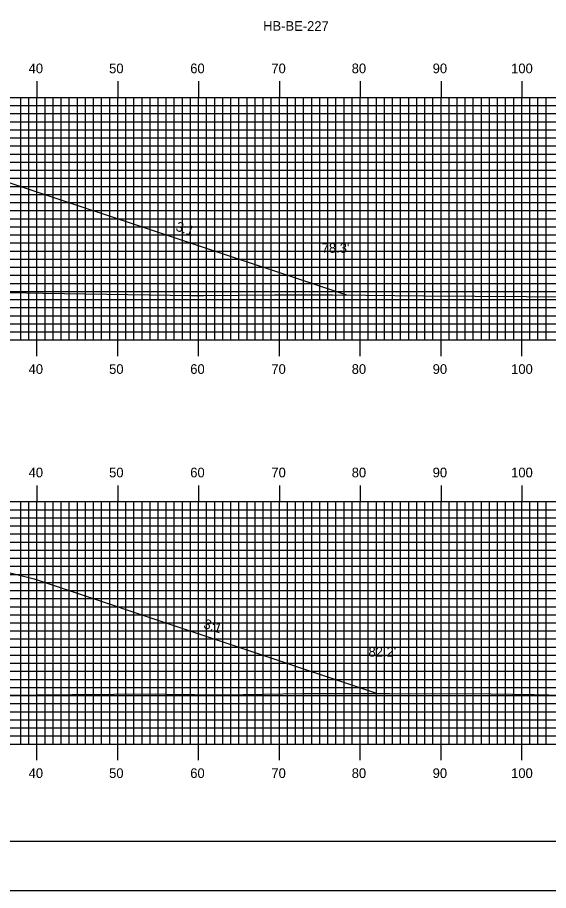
# Model space of a CAD drawing. Extents: x 1786976 to 1787319, y 442591 to 442811.
# Drawn here: x 1787179.2 to 1787244.9, y 442590.5 to 442698.6 of the extents above; entities that cross this region are included whole.
import ezdxf

# ---------------------------------------------------------------- set-up
doc = ezdxf.new("R2010")
doc.units = 0
for name, color, linetype in [('ANNOTATION', 7, 'Continuous'), ('BORDER', 7, 'Continuous'), ('BORING - NO REFUSAL', 7, 'Continuous'), ('D_Roadway_Centerline', 7, 'Continuous'), ('D_Roadway_SlopeLines', 7, 'Continuous'), ('D_Text_Standard', 7, 'Continuous'), ('H_V ANNOTATION', 7, 'Continuous'), ('MAJOR', 7, 'Continuous'), ('MINOR', 7, 'Continuous'), ('PLOT BOUNDARY', 7, 'Continuous'), ('S_Roadway_Centerline', 7, 'Continuous')]:
    doc.layers.add(name, color=color, linetype=linetype)

msp = doc.modelspace()

# ---------------------------------------------------------------- linework, layer by layer
at = {"layer": 'BORDER'}
msp.add_lwpolyline([(1786991.99, 442596.67), (1787311.99, 442596.67), (1787311.99, 442806.67), (1786991.99, 442806.67)], close=True, dxfattribs=at)
at = {"layer": 'D_Roadway_Centerline'}
for points in [[(1787075.17, 442666.66), (1787111.2, 442678.66), (1787118.59, 442681.13), (1787121.59, 442681.25), (1787129.59, 442681.57), (1787141.59, 442681.83), (1787153.59, 442682.1), (1787166.23, 442681.59), (1787174.6, 442679.18), (1787178.23, 442678.13), (1787219.9, 442664.24)], [(1787073.18, 442616.62), (1787111.2, 442629.29), (1787118.59, 442631.76), (1787121.59, 442631.88), (1787129.59, 442632.2), (1787141.59, 442632.46), (1787153.59, 442632.72), (1787169.26, 442632.1), (1787178.77, 442629.72), (1787181.26, 442629.1), (1787223.75, 442614.93)]]:
    msp.add_lwpolyline(points, dxfattribs=at)
at = {"layer": 'D_Roadway_SlopeLines'}
for points in [[(1787166.23, 442681.59), (1787178.23, 442678.13), (1787219.9, 442664.24)], [(1787169.26, 442632.1), (1787181.26, 442629.1), (1787223.75, 442614.93)]]:
    msp.add_lwpolyline(points, dxfattribs=at)
at = {"layer": 'MAJOR'}
for p, q in [((1787181.59, 442690.67), (1787181.59, 442688.67)), ((1787191.59, 442690.67), (1787191.59, 442688.67)), ((1787201.59, 442690.67), (1787201.59, 442688.67)), ((1787211.59, 442690.67), (1787211.59, 442688.67)), ((1787221.59, 442690.67), (1787221.59, 442688.67)), ((1787231.59, 442690.67), (1787231.59, 442688.67)), ((1787241.59, 442690.67), (1787241.59, 442688.67)), ((1787001.59, 442688.67), (1787281.59, 442688.67)), ((1787001.59, 442688.67), (1787281.59, 442688.67)), ((1787181.59, 442658.67), (1787181.59, 442688.67)), ((1787191.59, 442658.67), (1787191.59, 442688.67)), ((1787201.59, 442658.67), (1787201.59, 442688.67)), ((1787211.59, 442658.67), (1787211.59, 442688.67)), ((1787221.59, 442658.67), (1787221.59, 442688.67)), ((1787231.59, 442658.67), (1787231.59, 442688.67)), ((1787241.59, 442658.67), (1787241.59, 442688.67)), ((1787001.59, 442683.67), (1787281.59, 442683.67)), ((1787001.59, 442678.67), (1787281.59, 442678.67)), ((1787001.59, 442673.67), (1787281.59, 442673.67)), ((1787001.59, 442668.67), (1787281.59, 442668.67)), ((1787001.59, 442663.67), (1787281.59, 442663.67)), ((1787001.59, 442658.67), (1787281.59, 442658.67)), ((1787001.59, 442658.67), (1787281.59, 442658.67)), ((1787181.59, 442656.66), (1787181.59, 442658.67)), ((1787191.59, 442656.66), (1787191.59, 442658.67)), ((1787201.59, 442656.66), (1787201.59, 442658.67)), ((1787211.59, 442656.66), (1787211.59, 442658.67)), ((1787221.59, 442656.66), (1787221.59, 442658.67)), ((1787231.59, 442656.66), (1787231.59, 442658.67)), ((1787241.59, 442656.66), (1787241.59, 442658.67)), ((1787181.59, 442640.67), (1787181.59, 442638.67)), ((1787191.59, 442640.67), (1787191.59, 442638.67)), ((1787201.59, 442640.67), (1787201.59, 442638.67)), ((1787211.59, 442640.67), (1787211.59, 442638.67)), ((1787221.59, 442640.67), (1787221.59, 442638.67)), ((1787231.59, 442640.67), (1787231.59, 442638.67)), ((1787241.59, 442640.67), (1787241.59, 442638.67)), ((1787001.59, 442638.67), (1787281.59, 442638.67)), ((1787001.59, 442638.67), (1787281.59, 442638.67)), ((1787181.59, 442608.67), (1787181.59, 442638.67)), ((1787191.59, 442608.67), (1787191.59, 442638.67)), ((1787201.59, 442608.67), (1787201.59, 442638.67)), ((1787211.59, 442608.67), (1787211.59, 442638.67)), ((1787221.59, 442608.67), (1787221.59, 442638.67)), ((1787231.59, 442608.67), (1787231.59, 442638.67)), ((1787241.59, 442608.67), (1787241.59, 442638.67)), ((1787001.59, 442633.67), (1787281.59, 442633.67)), ((1787001.59, 442628.67), (1787281.59, 442628.67)), ((1787001.59, 442623.67), (1787281.59, 442623.67)), ((1787001.59, 442618.67), (1787281.59, 442618.67)), ((1787001.59, 442613.67), (1787281.59, 442613.67)), ((1787001.59, 442608.67), (1787281.59, 442608.67)), ((1787001.59, 442608.67), (1787281.59, 442608.67)), ((1787181.59, 442606.66), (1787181.59, 442608.67)), ((1787191.59, 442606.66), (1787191.59, 442608.67)), ((1787201.59, 442606.66), (1787201.59, 442608.67)), ((1787211.59, 442606.66), (1787211.59, 442608.67)), ((1787221.59, 442606.66), (1787221.59, 442608.67)), ((1787231.59, 442606.66), (1787231.59, 442608.67)), ((1787241.59, 442606.66), (1787241.59, 442608.67))]:
    msp.add_line(p, q, dxfattribs=at)
at = {"layer": 'MINOR'}
for p, q in [((1787179.59, 442658.67), (1787179.59, 442688.67)), ((1787180.59, 442658.67), (1787180.59, 442688.67)), ((1787182.59, 442658.67), (1787182.59, 442688.67)), ((1787183.59, 442658.67), (1787183.59, 442688.67)), ((1787184.59, 442658.67), (1787184.59, 442688.67)), ((1787185.59, 442658.67), (1787185.59, 442688.67)), ((1787186.59, 442658.67), (1787186.59, 442688.67)), ((1787187.59, 442658.67), (1787187.59, 442688.67)), ((1787188.59, 442658.67), (1787188.59, 442688.67)), ((1787189.59, 442658.67), (1787189.59, 442688.67)), ((1787190.59, 442658.67), (1787190.59, 442688.67)), ((1787192.59, 442658.67), (1787192.59, 442688.67)), ((1787193.59, 442658.67), (1787193.59, 442688.67)), ((1787194.59, 442658.67), (1787194.59, 442688.67)), ((1787195.59, 442658.67), (1787195.59, 442688.67)), ((1787196.59, 442658.67), (1787196.59, 442688.67)), ((1787197.59, 442658.67), (1787197.59, 442688.67)), ((1787198.59, 442658.67), (1787198.59, 442688.67)), ((1787199.59, 442658.67), (1787199.59, 442688.67)), ((1787200.59, 442658.67), (1787200.59, 442688.67)), ((1787202.59, 442658.67), (1787202.59, 442688.67)), ((1787203.59, 442658.67), (1787203.59, 442688.67)), ((1787204.59, 442658.67), (1787204.59, 442688.67)), ((1787205.59, 442658.67), (1787205.59, 442688.67)), ((1787206.59, 442658.67), (1787206.59, 442688.67)), ((1787207.59, 442658.67), (1787207.59, 442688.67)), ((1787208.59, 442658.67), (1787208.59, 442688.67)), ((1787209.59, 442658.67), (1787209.59, 442688.67)), ((1787210.59, 442658.67), (1787210.59, 442688.67)), ((1787212.59, 442658.67), (1787212.59, 442688.67)), ((1787213.59, 442658.67), (1787213.59, 442688.67)), ((1787214.59, 442658.67), (1787214.59, 442688.67)), ((1787215.59, 442658.67), (1787215.59, 442688.67)), ((1787216.59, 442658.67), (1787216.59, 442688.67)), ((1787217.59, 442658.67), (1787217.59, 442688.67)), ((1787218.59, 442658.67), (1787218.59, 442688.67)), ((1787219.59, 442658.67), (1787219.59, 442688.67)), ((1787220.59, 442658.67), (1787220.59, 442688.67)), ((1787222.59, 442658.67), (1787222.59, 442688.67)), ((1787223.59, 442658.67), (1787223.59, 442688.67)), ((1787224.59, 442658.67), (1787224.59, 442688.67)), ((1787225.59, 442658.67), (1787225.59, 442688.67)), ((1787226.59, 442658.67), (1787226.59, 442688.67)), ((1787227.59, 442658.67), (1787227.59, 442688.67)), ((1787228.59, 442658.67), (1787228.59, 442688.67)), ((1787229.59, 442658.67), (1787229.59, 442688.67)), ((1787230.59, 442658.67), (1787230.59, 442688.67)), ((1787232.59, 442658.67), (1787232.59, 442688.67)), ((1787233.59, 442658.67), (1787233.59, 442688.67)), ((1787234.59, 442658.67), (1787234.59, 442688.67)), ((1787235.59, 442658.67), (1787235.59, 442688.67)), ((1787236.59, 442658.67), (1787236.59, 442688.67)), ((1787237.59, 442658.67), (1787237.59, 442688.67)), ((1787238.59, 442658.67), (1787238.59, 442688.67)), ((1787239.59, 442658.67), (1787239.59, 442688.67)), ((1787240.59, 442658.67), (1787240.59, 442688.67)), ((1787242.59, 442658.67), (1787242.59, 442688.67)), ((1787243.59, 442658.67), (1787243.59, 442688.67)), ((1787244.59, 442658.67), (1787244.59, 442688.67)), ((1787001.59, 442687.67), (1787281.59, 442687.67)), ((1787001.59, 442686.67), (1787281.59, 442686.67)), ((1787001.59, 442685.67), (1787281.59, 442685.67)), ((1787001.59, 442684.67), (1787281.59, 442684.67)), ((1787001.59, 442682.67), (1787281.59, 442682.67)), ((1787001.59, 442681.67), (1787281.59, 442681.67)), ((1787001.59, 442680.67), (1787281.59, 442680.67)), ((1787001.59, 442679.67), (1787281.59, 442679.67)), ((1787001.59, 442677.67), (1787281.59, 442677.67)), ((1787001.59, 442676.67), (1787281.59, 442676.67)), ((1787001.59, 442675.67), (1787281.59, 442675.67)), ((1787001.59, 442674.67), (1787281.59, 442674.67)), ((1787001.59, 442672.67), (1787281.59, 442672.67)), ((1787001.59, 442671.67), (1787281.59, 442671.67)), ((1787001.59, 442670.67), (1787281.59, 442670.67)), ((1787001.59, 442669.67), (1787281.59, 442669.67)), ((1787001.59, 442667.67), (1787281.59, 442667.67)), ((1787001.59, 442666.67), (1787281.59, 442666.67)), ((1787001.59, 442665.67), (1787281.59, 442665.67)), ((1787001.59, 442664.67), (1787281.59, 442664.67)), ((1787001.59, 442662.67), (1787281.59, 442662.67)), ((1787001.59, 442661.67), (1787281.59, 442661.67)), ((1787001.59, 442660.67), (1787281.59, 442660.67)), ((1787001.59, 442659.67), (1787281.59, 442659.67)), ((1787179.59, 442608.67), (1787179.59, 442638.67)), ((1787180.59, 442608.67), (1787180.59, 442638.67)), ((1787182.59, 442608.67), (1787182.59, 442638.67)), ((1787183.59, 442608.67), (1787183.59, 442638.67)), ((1787184.59, 442608.67), (1787184.59, 442638.67)), ((1787185.59, 442608.67), (1787185.59, 442638.67)), ((1787186.59, 442608.67), (1787186.59, 442638.67)), ((1787187.59, 442608.67), (1787187.59, 442638.67)), ((1787188.59, 442608.67), (1787188.59, 442638.67)), ((1787189.59, 442608.67), (1787189.59, 442638.67)), ((1787190.59, 442608.67), (1787190.59, 442638.67)), ((1787192.59, 442608.67), (1787192.59, 442638.67)), ((1787193.59, 442608.67), (1787193.59, 442638.67)), ((1787194.59, 442608.67), (1787194.59, 442638.67)), ((1787195.59, 442608.67), (1787195.59, 442638.67)), ((1787196.59, 442608.67), (1787196.59, 442638.67)), ((1787197.59, 442608.67), (1787197.59, 442638.67)), ((1787198.59, 442608.67), (1787198.59, 442638.67)), ((1787199.59, 442608.67), (1787199.59, 442638.67)), ((1787200.59, 442608.67), (1787200.59, 442638.67)), ((1787202.59, 442608.67), (1787202.59, 442638.67)), ((1787203.59, 442608.67), (1787203.59, 442638.67)), ((1787204.59, 442608.67), (1787204.59, 442638.67)), ((1787205.59, 442608.67), (1787205.59, 442638.67)), ((1787206.59, 442608.67), (1787206.59, 442638.67)), ((1787207.59, 442608.67), (1787207.59, 442638.67)), ((1787208.59, 442608.67), (1787208.59, 442638.67)), ((1787209.59, 442608.67), (1787209.59, 442638.67)), ((1787210.59, 442608.67), (1787210.59, 442638.67)), ((1787212.59, 442608.67), (1787212.59, 442638.67)), ((1787213.59, 442608.67), (1787213.59, 442638.67)), ((1787214.59, 442608.67), (1787214.59, 442638.67)), ((1787215.59, 442608.67), (1787215.59, 442638.67)), ((1787216.59, 442608.67), (1787216.59, 442638.67)), ((1787217.59, 442608.67), (1787217.59, 442638.67)), ((1787218.59, 442608.67), (1787218.59, 442638.67)), ((1787219.59, 442608.67), (1787219.59, 442638.67)), ((1787220.59, 442608.67), (1787220.59, 442638.67)), ((1787222.59, 442608.67), (1787222.59, 442638.67)), ((1787223.59, 442608.67), (1787223.59, 442638.67)), ((1787224.59, 442608.67), (1787224.59, 442638.67)), ((1787225.59, 442608.67), (1787225.59, 442638.67)), ((1787226.59, 442608.67), (1787226.59, 442638.67)), ((1787227.59, 442608.67), (1787227.59, 442638.67)), ((1787228.59, 442608.67), (1787228.59, 442638.67)), ((1787229.59, 442608.67), (1787229.59, 442638.67)), ((1787230.59, 442608.67), (1787230.59, 442638.67)), ((1787232.59, 442608.67), (1787232.59, 442638.67)), ((1787233.59, 442608.67), (1787233.59, 442638.67)), ((1787234.59, 442608.67), (1787234.59, 442638.67)), ((1787235.59, 442608.67), (1787235.59, 442638.67)), ((1787236.59, 442608.67), (1787236.59, 442638.67)), ((1787237.59, 442608.67), (1787237.59, 442638.67)), ((1787238.59, 442608.67), (1787238.59, 442638.67)), ((1787239.59, 442608.67), (1787239.59, 442638.67)), ((1787240.59, 442608.67), (1787240.59, 442638.67)), ((1787242.59, 442608.67), (1787242.59, 442638.67)), ((1787243.59, 442608.67), (1787243.59, 442638.67)), ((1787244.59, 442608.67), (1787244.59, 442638.67)), ((1787001.59, 442637.67), (1787281.59, 442637.67)), ((1787001.59, 442636.67), (1787281.59, 442636.67)), ((1787001.59, 442635.67), (1787281.59, 442635.67)), ((1787001.59, 442634.67), (1787281.59, 442634.67)), ((1787001.59, 442632.67), (1787281.59, 442632.67)), ((1787001.59, 442631.67), (1787281.59, 442631.67)), ((1787001.59, 442630.67), (1787281.59, 442630.67)), ((1787001.59, 442629.67), (1787281.59, 442629.67)), ((1787001.59, 442627.67), (1787281.59, 442627.67)), ((1787001.59, 442626.67), (1787281.59, 442626.67)), ((1787001.59, 442625.67), (1787281.59, 442625.67)), ((1787001.59, 442624.67), (1787281.59, 442624.67)), ((1787001.59, 442622.67), (1787281.59, 442622.67)), ((1787001.59, 442621.67), (1787281.59, 442621.67)), ((1787001.59, 442620.67), (1787281.59, 442620.67)), ((1787001.59, 442619.67), (1787281.59, 442619.67)), ((1787001.59, 442617.67), (1787281.59, 442617.67)), ((1787001.59, 442616.67), (1787281.59, 442616.67)), ((1787001.59, 442615.67), (1787281.59, 442615.67)), ((1787001.59, 442614.67), (1787281.59, 442614.67)), ((1787001.59, 442612.67), (1787281.59, 442612.67)), ((1787001.59, 442611.67), (1787281.59, 442611.67)), ((1787001.59, 442610.67), (1787281.59, 442610.67)), ((1787001.59, 442609.67), (1787281.59, 442609.67))]:
    msp.add_line(p, q, dxfattribs=at)
at = {"layer": 'PLOT BOUNDARY'}
msp.add_lwpolyline([(1786975.8, 442590.55), (1787315.8, 442590.55), (1787315.8, 442810.55), (1786975.8, 442810.55)], close=True, dxfattribs=at)
at = {"layer": 'S_Roadway_Centerline'}
for points in [[(1787171.93, 442664.67), (1787182.34, 442664.47), (1787200.72, 442664.18), (1787201.57, 442664.17), (1787202.18, 442664.16), (1787211, 442664.25), (1787218.19, 442664.24), (1787222.27, 442664.23), (1787229.46, 442664.14), (1787242.18, 442664.04), (1787248.78, 442664.02), (1787258.29, 442664.07), (1787262.4, 442664.07), (1787264.7, 442664.07), (1787276.96, 442664.02), (1787281.59, 442664)], [(1787177.27, 442614.71), (1787185.92, 442614.82), (1787196.31, 442614.87), (1787197.54, 442614.84), (1787204.65, 442614.76), (1787214.46, 442614.94), (1787217.7, 442614.94), (1787225.22, 442614.93), (1787237.74, 442614.87), (1787243.12, 442614.8), (1787257.71, 442614.46), (1787271.3, 442614.07), (1787275.05, 442613.91), (1787277.58, 442613.95), (1787281.59, 442614.05)]]:
    msp.add_lwpolyline(points, dxfattribs=at)

# ---------------------------------------------------------------- texts
at = {"layer": 'ANNOTATION'}
for p in [(1787198.67, 442672.22), (1787202.11, 442623.06)]:
    msp.add_text('3:1', height=1.2, rotation=341.5652, dxfattribs=at).set_placement(p)
at = {"layer": 'BORING - NO REFUSAL'}
msp.add_text('HB-BE-227', height=1.2, rotation=359.8142, dxfattribs=at).set_placement((1787209.58, 442696.93))
at = {"layer": 'D_Text_Standard'}
for s, p in [("78.3'", (1787216.83, 442669.45)), ("82.2'", (1787222.62, 442619.48))]:
    msp.add_text(s, height=1.2, dxfattribs=at).set_placement(p)
at = {"layer": 'H_V ANNOTATION'}
for s, p in [('40', (1787180.56, 442691.67)), ('50', (1787190.52, 442691.67)), ('60', (1787200.56, 442691.67)), ('70', (1787210.6, 442691.67)), ('80', (1787220.54, 442691.67)), ('90', (1787230.56, 442691.67)), ('100', (1787240.27, 442691.67)), ('40', (1787180.56, 442654.47)), ('50', (1787190.52, 442654.47)), ('60', (1787200.56, 442654.47)), ('70', (1787210.6, 442654.47)), ('80', (1787220.54, 442654.47)), ('90', (1787230.56, 442654.47)), ('100', (1787240.27, 442654.47)), ('40', (1787180.56, 442641.67)), ('50', (1787190.52, 442641.67)), ('60', (1787200.56, 442641.67)), ('70', (1787210.6, 442641.67)), ('80', (1787220.54, 442641.67)), ('90', (1787230.56, 442641.67)), ('100', (1787240.27, 442641.67)), ('40', (1787180.56, 442604.47)), ('50', (1787190.52, 442604.47)), ('60', (1787200.56, 442604.47)), ('70', (1787210.6, 442604.47)), ('80', (1787220.54, 442604.47)), ('90', (1787230.56, 442604.47)), ('100', (1787240.27, 442604.47))]:
    msp.add_text(s, height=1.2, dxfattribs=at).set_placement(p)

doc.saveas('drawing.dxf')
